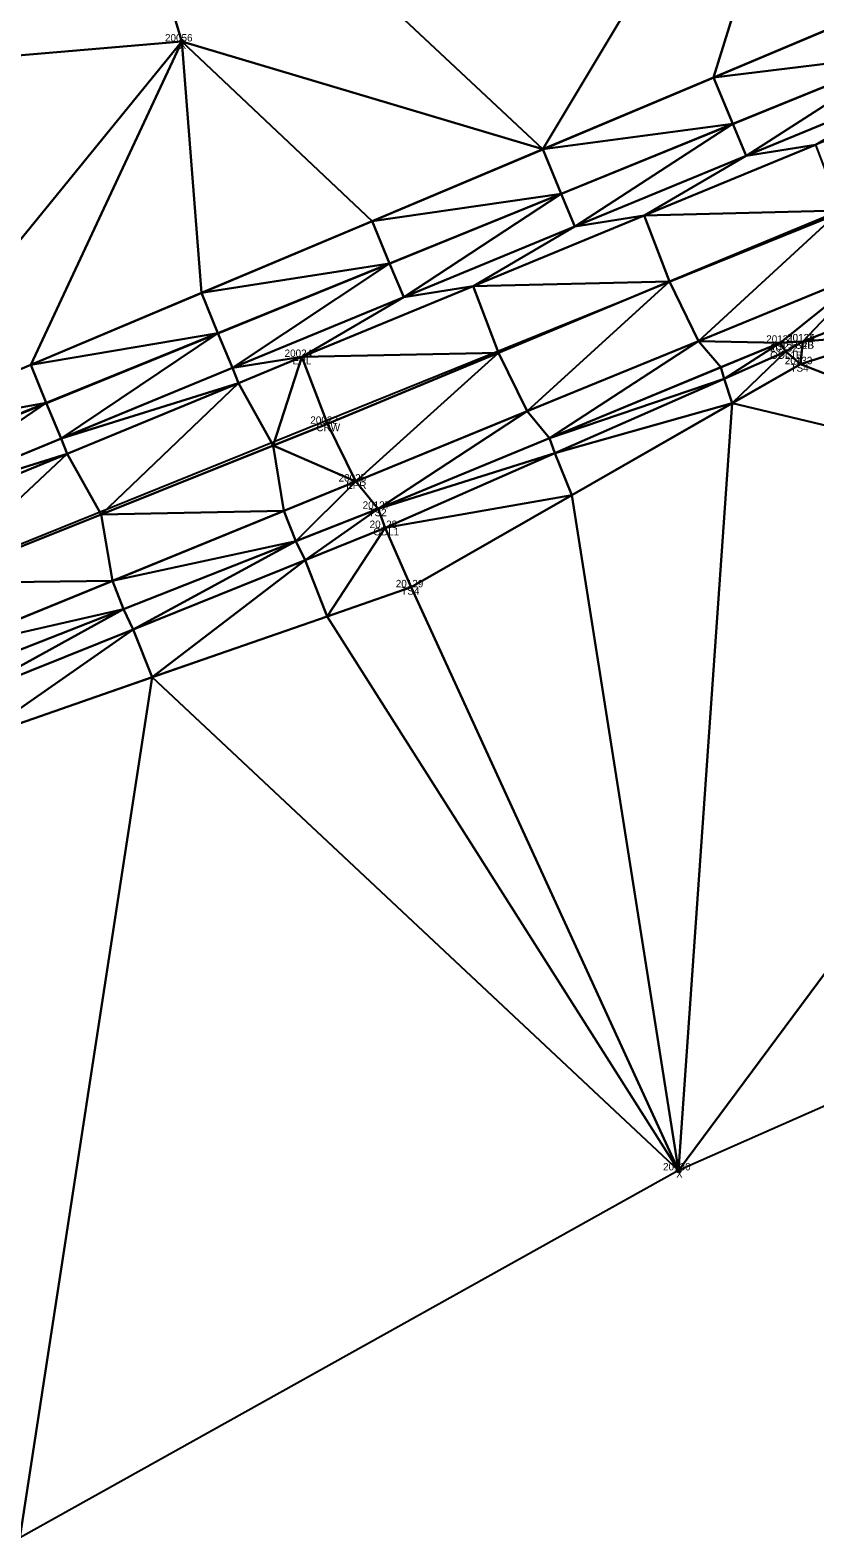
# Model space of a CAD drawing. Extents: x 1966740 to 1969291, y 1117379 to 1118460.
# Drawn here: x 1966934.5 to 1967040.4, y 1117379.7 to 1117583 of the extents above; entities that cross this region are included whole.
import ezdxf

# ---------------------------------------------------------------- set-up
doc = ezdxf.new("R2010")
doc.units = 0
for name, color, linetype in [('Level 1', 7, 'Continuous'), ('Level 3', 7, 'Continuous'), ('Level 30', 7, 'Continuous'), ('Level 35', 7, 'Continuous'), ('Level 50', 7, 'Continuous'), ('Level 52', 7, 'Continuous'), ('Level 53', 7, 'Continuous'), ('Level 6', 7, 'Continuous'), ('Level 62', 7, 'Continuous')]:
    doc.layers.add(name, color=color, linetype=linetype)

msp = doc.modelspace()

# ---------------------------------------------------------------- linework, layer by layer
at = {"layer": 'Level 1'}
msp.add_line((1966770.74, 1117448.12), (1967849.47, 1117883.86), dxfattribs=at)
at = {"layer": 'Level 3'}
for points in [[(1966768.15, 1117461.43), (1966869.41, 1117499.34), (1967070.52, 1117582.35), (1967171.25, 1117624.02), (1967269.74, 1117664.9), (1967320.21, 1117685.71), (1967369.37, 1117708.48), (1967468.51, 1117746.66), (1967564.6, 1117784.47), (1967654.68, 1117828.05), (1967680.1, 1117841.48), (1967687.91, 1117842.93), (1967691.45, 1117838.71), (1967693.03, 1117834.22)], [(1966769.51, 1117457.48), (1966870.16, 1117497.34), (1966971.19, 1117538.95), (1967071.09, 1117580.24), (1967172.6, 1117621.53), (1967270.79, 1117661.66), (1967321.12, 1117682.57), (1967371.52, 1117702.88), (1967470.26, 1117741.55), (1967566.67, 1117779.5), (1967661.25, 1117817.53), (1967694.4, 1117831.19), (1967697.89, 1117822.8)], [(1966772.57, 1117449.88), (1966874.49, 1117489.87), (1966974.64, 1117529.93), (1967075.06, 1117571.68), (1967175.91, 1117613.34), (1967274.11, 1117653.69), (1967325.25, 1117674.8), (1967374.73, 1117695.01), (1967473.9, 1117733.1), (1967569.8, 1117771.9), (1967665.19, 1117809.79), (1967697.89, 1117822.8)], [(1966766.42, 1117472.19), (1966865.47, 1117508.82), (1967066.64, 1117593.45), (1967166.55, 1117636.11), (1967264.62, 1117677.56), (1967315.66, 1117698.57), (1967367.9, 1117716.34), (1967464.92, 1117753.87), (1967560.73, 1117793.63)], [(1966775.75, 1117440.57), (1966876.18, 1117480.39), (1966978.46, 1117522.15), (1967078.26, 1117563.06), (1967180.7, 1117605.06), (1967277.98, 1117644.72), (1967308.82, 1117656.67)], [(1966786.01, 1117438.62), (1966877.32, 1117477.51), (1966981.49, 1117518.47), (1967035.72, 1117540.87), (1967038.77, 1117541.05)], [(1966789.47, 1117432.06), (1966880.12, 1117471.13), (1966985.94, 1117507.88), (1967038.45, 1117537.97), (1967038.77, 1117541.05)]]:
    msp.add_lwpolyline(points, dxfattribs=at)
at = {"layer": 'Level 30'}
for centre in [(1966955, 1117581.5), (1967022.01, 1117429.23)]:
    msp.add_circle(centre, 0.25, dxfattribs=at)
at = {"layer": 'Level 35'}
for points in [[(1966942.02, 1117624.67), (1967045.28, 1117636.33), (1967003.71, 1117566.97)], [(1967003.71, 1117566.97), (1967045.28, 1117636.33), (1967026.74, 1117576.66)], [(1967026.74, 1117576.66), (1967045.28, 1117636.33), (1967049.78, 1117586.36)], [(1966849.57, 1117572.49), (1966942.02, 1117624.67), (1966955, 1117581.5)], [(1966942.02, 1117624.67), (1967003.71, 1117566.97), (1966955, 1117581.5)], [(1967026.74, 1117576.66), (1967049.78, 1117586.36), (1967052.47, 1117579.79)], [(1966849.57, 1117572.49), (1966955, 1117581.5), (1966911.55, 1117528.2)], [(1966911.55, 1117528.2), (1966955, 1117581.5), (1966934.59, 1117537.89)], [(1966934.59, 1117537.89), (1966955, 1117581.5), (1966957.63, 1117547.59)], [(1966955, 1117581.5), (1967003.71, 1117566.97), (1966980.67, 1117557.28)], [(1966955, 1117581.5), (1966980.67, 1117557.28), (1966957.63, 1117547.59)], [(1967026.74, 1117576.66), (1967052.47, 1117579.79), (1967029.32, 1117570.38)], [(1967029.32, 1117570.38), (1967052.47, 1117579.79), (1967031.12, 1117566.09)], [(1967031.12, 1117566.09), (1967052.47, 1117579.79), (1967054.23, 1117575.62)], [(1967003.71, 1117566.97), (1967026.74, 1117576.66), (1967029.32, 1117570.38)], [(1967031.12, 1117566.09), (1967054.23, 1117575.62), (1967040.46, 1117567.58)], [(1967003.71, 1117566.97), (1967029.32, 1117570.38), (1967006.16, 1117560.97)], [(1967006.16, 1117560.97), (1967029.32, 1117570.38), (1967008.02, 1117556.55)], [(1967008.02, 1117556.55), (1967029.32, 1117570.38), (1967031.12, 1117566.09)], [(1966980.67, 1117557.28), (1967003.71, 1117566.97), (1967006.16, 1117560.97)], [(1967017.37, 1117558.04), (1967031.12, 1117566.09), (1967040.46, 1117567.58)], [(1967017.37, 1117558.04), (1967040.46, 1117567.58), (1967043.85, 1117558.71)], [(1967008.02, 1117556.55), (1967031.12, 1117566.09), (1967017.37, 1117558.04)], [(1966980.67, 1117557.28), (1967006.16, 1117560.97), (1966983.01, 1117551.56)], [(1966983.01, 1117551.56), (1967006.16, 1117560.97), (1966984.92, 1117547.02)], [(1966984.92, 1117547.02), (1967006.16, 1117560.97), (1967008.02, 1117556.55)], [(1967017.37, 1117558.04), (1967043.85, 1117558.71), (1967020.78, 1117549.12)], [(1967020.78, 1117549.12), (1967043.85, 1117558.71), (1967024.7, 1117541.1)], [(1967024.7, 1117541.1), (1967043.85, 1117558.71), (1967047.82, 1117550.58)], [(1966957.63, 1117547.59), (1966980.67, 1117557.28), (1966983.01, 1117551.56)], [(1966984.92, 1117547.02), (1967008.02, 1117556.55), (1966994.28, 1117548.5)], [(1966994.28, 1117548.5), (1967008.02, 1117556.55), (1967017.37, 1117558.04)], [(1966994.28, 1117548.5), (1967017.37, 1117558.04), (1967020.78, 1117549.12)], [(1966957.63, 1117547.59), (1966983.01, 1117551.56), (1966959.86, 1117542.15)], [(1966959.86, 1117542.15), (1966983.01, 1117551.56), (1966961.82, 1117537.48)], [(1966961.82, 1117537.48), (1966983.01, 1117551.56), (1966984.92, 1117547.02)], [(1967024.7, 1117541.1), (1967047.82, 1117550.58), (1967035.72, 1117540.87)], [(1967035.72, 1117540.87), (1967047.82, 1117550.58), (1967038.77, 1117541.05)], [(1967038.77, 1117541.05), (1967047.82, 1117550.58), (1967048.76, 1117544.94)], [(1966971.19, 1117538.95), (1966984.92, 1117547.02), (1966994.28, 1117548.5)], [(1966971.19, 1117538.95), (1966994.28, 1117548.5), (1966997.71, 1117539.52)], [(1966994.28, 1117548.5), (1967020.78, 1117549.12), (1966997.71, 1117539.52)], [(1966997.71, 1117539.52), (1967020.78, 1117549.12), (1967001.58, 1117531.63)], [(1967001.58, 1117531.63), (1967020.78, 1117549.12), (1967024.7, 1117541.1)], [(1966934.59, 1117537.89), (1966957.63, 1117547.59), (1966959.86, 1117542.15)], [(1966961.82, 1117537.48), (1966984.92, 1117547.02), (1966971.19, 1117538.95)], [(1967038.77, 1117541.05), (1967048.76, 1117544.94), (1967051.21, 1117542.08)], [(1966934.59, 1117537.89), (1966959.86, 1117542.15), (1966936.7, 1117532.74)], [(1966936.7, 1117532.74), (1966959.86, 1117542.15), (1966938.72, 1117527.95)], [(1966938.72, 1117527.95), (1966959.86, 1117542.15), (1966961.82, 1117537.48)], [(1967001.58, 1117531.63), (1967024.7, 1117541.1), (1967004.59, 1117528.01)], [(1967004.59, 1117528.01), (1967024.7, 1117541.1), (1967027.69, 1117537.55)], [(1967024.7, 1117541.1), (1967035.72, 1117540.87), (1967027.69, 1117537.55)], [(1967027.69, 1117537.55), (1967035.72, 1117540.87), (1967028.17, 1117536.02)], [(1967028.17, 1117536.02), (1967035.72, 1117540.87), (1967036.47, 1117539.68)], [(1967035.72, 1117540.87), (1967038.77, 1117541.05), (1967036.47, 1117539.68)], [(1967036.47, 1117539.68), (1967038.77, 1117541.05), (1967038.45, 1117537.97)], [(1967038.45, 1117537.97), (1967038.77, 1117541.05), (1967051.21, 1117542.08)], [(1967038.45, 1117537.97), (1967051.21, 1117542.08), (1967088.4, 1117518.58)], [(1966961.82, 1117537.48), (1966971.19, 1117538.95), (1966962.61, 1117535.42)], [(1966962.61, 1117535.42), (1966971.19, 1117538.95), (1966967.32, 1117527)], [(1966967.32, 1117527), (1966971.19, 1117538.95), (1966974.64, 1117529.93)], [(1966971.19, 1117538.95), (1966997.71, 1117539.52), (1966974.64, 1117529.93)], [(1966974.64, 1117529.93), (1966997.71, 1117539.52), (1966978.46, 1117522.15)], [(1966978.46, 1117522.15), (1966997.71, 1117539.52), (1967001.58, 1117531.63)], [(1967028.17, 1117536.02), (1967036.47, 1117539.68), (1967029.25, 1117532.7)], [(1967029.25, 1117532.7), (1967036.47, 1117539.68), (1967038.45, 1117537.97)], [(1966911.55, 1117528.2), (1966934.59, 1117537.89), (1966936.7, 1117532.74)], [(1966938.72, 1117527.95), (1966961.82, 1117537.48), (1966962.61, 1117535.42)], [(1967004.59, 1117528.01), (1967027.69, 1117537.55), (1967028.17, 1117536.02)], [(1967029.25, 1117532.7), (1967038.45, 1117537.97), (1967088.4, 1117518.58)], [(1966938.72, 1117527.95), (1966962.61, 1117535.42), (1966939.5, 1117525.9)], [(1966939.5, 1117525.9), (1966962.61, 1117535.42), (1966944.11, 1117517.72)], [(1966944.11, 1117517.72), (1966962.61, 1117535.42), (1966967.32, 1117527)], [(1967004.59, 1117528.01), (1967028.17, 1117536.02), (1967005.3, 1117525.95)], [(1967005.3, 1117525.95), (1967028.17, 1117536.02), (1967029.25, 1117532.7)], [(1966911.55, 1117528.2), (1966936.7, 1117532.74), (1966913.55, 1117523.32)], [(1966913.55, 1117523.32), (1966936.7, 1117532.74), (1966915.62, 1117518.41)], [(1966915.62, 1117518.41), (1966936.7, 1117532.74), (1966938.72, 1117527.95)], [(1967005.3, 1117525.95), (1967029.25, 1117532.7), (1967007.59, 1117520.29)], [(1967007.59, 1117520.29), (1967029.25, 1117532.7), (1967022.01, 1117429.23)], [(1967022.01, 1117429.23), (1967029.25, 1117532.7), (1967088.4, 1117518.58)], [(1966978.46, 1117522.15), (1967001.58, 1117531.63), (1966981.49, 1117518.47)], [(1966981.49, 1117518.47), (1967001.58, 1117531.63), (1967004.59, 1117528.01)], [(1966967.32, 1117527), (1966974.64, 1117529.93), (1966978.46, 1117522.15)], [(1966915.62, 1117518.41), (1966938.72, 1117527.95), (1966939.5, 1117525.9)], [(1966944.11, 1117517.72), (1966967.32, 1117527), (1966968.75, 1117518.18)], [(1966967.32, 1117527), (1966978.46, 1117522.15), (1966968.75, 1117518.18)], [(1966981.49, 1117518.47), (1967004.59, 1117528.01), (1967005.3, 1117525.95)], [(1966915.62, 1117518.41), (1966939.5, 1117525.9), (1966916.39, 1117516.38)], [(1966916.39, 1117516.38), (1966939.5, 1117525.9), (1966920.9, 1117508.44)], [(1966920.9, 1117508.44), (1966939.5, 1117525.9), (1966944.11, 1117517.72)], [(1966981.49, 1117518.47), (1967005.3, 1117525.95), (1966982.42, 1117515.88)], [(1966982.42, 1117515.88), (1967005.3, 1117525.95), (1967007.59, 1117520.29)], [(1966968.75, 1117518.18), (1966978.46, 1117522.15), (1966970.36, 1117514.1)], [(1966970.36, 1117514.1), (1966978.46, 1117522.15), (1966981.49, 1117518.47)], [(1966982.42, 1117515.88), (1967007.59, 1117520.29), (1966985.94, 1117507.88)], [(1966985.94, 1117507.88), (1967007.59, 1117520.29), (1967022.01, 1117429.23)], [(1966944.11, 1117517.72), (1966968.75, 1117518.18), (1966945.61, 1117508.74)], [(1966945.61, 1117508.74), (1966968.75, 1117518.18), (1966970.36, 1117514.1)], [(1966970.36, 1117514.1), (1966981.49, 1117518.47), (1966971.61, 1117511.53)], [(1966971.61, 1117511.53), (1966981.49, 1117518.47), (1966982.42, 1117515.88)], [(1967022.01, 1117429.23), (1967088.4, 1117518.58), (1967106.21, 1117466.35)], [(1966920.9, 1117508.44), (1966944.11, 1117517.72), (1966945.61, 1117508.74)], [(1966971.61, 1117511.53), (1966982.42, 1117515.88), (1966974.59, 1117503.94)], [(1966974.59, 1117503.94), (1966982.42, 1117515.88), (1966985.94, 1117507.88)], [(1966945.61, 1117508.74), (1966970.36, 1117514.1), (1966947.1, 1117504.95)], [(1966947.1, 1117504.95), (1966970.36, 1117514.1), (1966948.42, 1117502.21)], [(1966948.42, 1117502.21), (1966970.36, 1117514.1), (1966971.61, 1117511.53)], [(1966948.42, 1117502.21), (1966971.61, 1117511.53), (1966950.97, 1117495.74)], [(1966950.97, 1117495.74), (1966971.61, 1117511.53), (1966974.59, 1117503.94)], [(1966920.9, 1117508.44), (1966945.61, 1117508.74), (1966922.47, 1117499.29)], [(1966922.47, 1117499.29), (1966945.61, 1117508.74), (1966947.1, 1117504.95)], [(1966974.59, 1117503.94), (1966985.94, 1117507.88), (1967022.01, 1117429.23)], [(1966922.47, 1117499.29), (1966947.1, 1117504.95), (1966923.84, 1117495.8)], [(1966923.84, 1117495.8), (1966947.1, 1117504.95), (1966925.22, 1117492.89)], [(1966925.22, 1117492.89), (1966947.1, 1117504.95), (1966948.42, 1117502.21)], [(1966950.97, 1117495.74), (1966974.59, 1117503.94), (1967022.01, 1117429.23)], [(1966925.22, 1117492.89), (1966948.42, 1117502.21), (1966927.35, 1117487.53)], [(1966927.35, 1117487.53), (1966948.42, 1117502.21), (1966950.97, 1117495.74)], [(1966927.35, 1117487.53), (1966950.97, 1117495.74), (1966933.11, 1117379.67)], [(1966933.11, 1117379.67), (1966950.97, 1117495.74), (1967022.01, 1117429.23)]]:
    msp.add_lwpolyline(points, close=True, dxfattribs=at)
at = {"layer": 'Level 50'}
for centre in [(1967035.72, 1117540.87), (1967038.77, 1117541.05), (1967038.77, 1117541.05), (1966971.19, 1117538.95), (1967036.47, 1117539.68), (1967038.45, 1117537.97), (1966974.64, 1117529.93), (1966978.46, 1117522.15), (1966981.49, 1117518.47), (1966982.42, 1117515.88), (1966985.94, 1117507.88)]:
    msp.add_circle(centre, 0.001, dxfattribs=at)
at = {"layer": 'Level 6'}
for points in [[(1966766.64, 1117466.58), (1966867.24, 1117504.5), (1967068.76, 1117586.41), (1967167.95, 1117632.67), (1967266.82, 1117671.88), (1967316.79, 1117693.47), (1967368.01, 1117713.34), (1967465.67, 1117751.74), (1967560.73, 1117793.63)], [(1966787.6, 1117435.18), (1966878.84, 1117474.24), (1966982.42, 1117515.88), (1967036.47, 1117539.68)]]:
    msp.add_lwpolyline(points, dxfattribs=at)

# ---------------------------------------------------------------- texts
at = {"layer": 'Level 52'}
for s, p in [('20056', (1966952.71, 1117581.5)), ('20130', (1967019.91, 1117429.23))]:
    msp.add_text(s, height=1, dxfattribs=at).set_placement(p)
at = {"layer": 'Level 53'}
for s, p in [('20131', (1967033.83, 1117540.87)), ('TS2', (1967034.39, 1117539.87)), ('20132', (1967034.36, 1117539.68)), ('20134', (1967036.64, 1117541.05)), ('20135', (1967036.66, 1117541.05)), ('TS4B', (1967036.92, 1117540.05)), ('TS2B', (1967036.95, 1117540.05)), ('20024', (1966968.85, 1117538.95)), ('EPL', (1966969.94, 1117537.95)), ('ODL1B', (1967034.36, 1117538.68)), ('20133', (1967036.34, 1117537.97)), ('TS4', (1967037.1, 1117536.97)), ('20022', (1966972.32, 1117529.93)), ('CRW', (1966973.14, 1117528.93)), ('20025', (1966976.14, 1117522.15)), ('EPR', (1966977.15, 1117521.15)), ('20127', (1966979.38, 1117518.47)), ('TS2', (1966980.17, 1117517.47)), ('20128', (1966980.32, 1117515.88)), ('ODL1', (1966980.82, 1117514.88)), ('20129', (1966983.85, 1117507.88)), ('TS4', (1966984.59, 1117506.88))]:
    msp.add_text(s, height=1, dxfattribs=at).set_placement(p)
at = {"layer": 'Level 62'}
for p in [(1966954.67, 1117580.5), (1967021.68, 1117428.23)]:
    msp.add_text('X', height=1, dxfattribs=at).set_placement(p)

doc.saveas('drawing.dxf')
